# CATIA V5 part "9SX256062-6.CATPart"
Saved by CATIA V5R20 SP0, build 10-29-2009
Part number: 9SX256062-6
Revision: ANY
Definition: UNKNOWN
Nomenclature: 9SX256062-6
Source: Unknown
Bounding box of the stored display mesh (mm): x -30 to 30, y -30 to 30, z 4 to 66
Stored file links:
  C:\Users\Utente\Desktop\IO LAVORO\3D X SITO CF\CUMSA\3D files SX.256062\SX 256062\9SX256062-6.CATPart
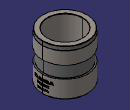
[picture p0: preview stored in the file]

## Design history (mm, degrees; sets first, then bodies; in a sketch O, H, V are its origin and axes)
Body1 "Envolver1" (main body)
  Solid1: solid without history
